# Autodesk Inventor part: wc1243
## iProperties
Shininess: 64.0
Length Units: 11272
Angle Units: 11279
Time Units: 11290
Mass Units: 11286
Length Display Precision: 3
Angle Display Precision: 2
Compacted: True
Part Number: wc1243
Document SubType Name: Modeling
Created: 2004-08
Designer: John Blackburn
Manufacturer: Standard
Standards Organization: Custom
Material: Aluminum-6061
Density: 0.0
Volumn: 0.0
Area: 0.0
PropertySet Name: Model Information
Control State: 0
Master: False
Checked Out: False
Author: John Blackburn
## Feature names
1. Base1
